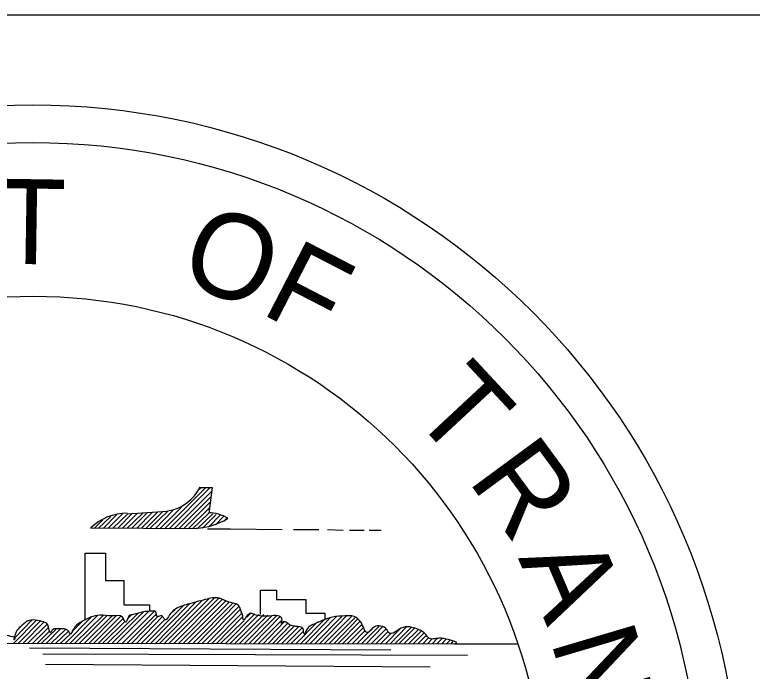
# Model space of a CAD drawing. Extents: x 1458004.1 to 1458040.9, y 194172.7 to 194198.1.
# Drawn here: x 1458033.012 to 1458033.917, y 194177.242 to 194178.047 of the extents above; entities that cross this region are included whole.
import ezdxf

# ---------------------------------------------------------------- set-up
doc = ezdxf.new("R2010")
doc.units = 0
for name, color, linetype in [('ODOT_Seal_0', 7, 'Continuous'), ('ODOT_Seal_1', 7, 'Continuous'), ('ODOT_Seal_2', 7, 'Continuous'), ('Text_Box_4', 7, 'Continuous')]:
    doc.layers.add(name, color=color, linetype=linetype)

msp = doc.modelspace()

# ---------------------------------------------------------------- linework, layer by layer
at = {"layer": 'ODOT_Seal_0'}
for p, q in [((1458033.235, 194177.41667), (1458033.105, 194177.4175)), ((1458033.24833, 194177.41667), (1458033.27667, 194177.41667)), ((1458033.27667, 194177.41667), (1458033.34, 194177.41583)), ((1458033.35417, 194177.41583), (1458033.385, 194177.41583)), ((1458033.39583, 194177.41583), (1458033.415, 194177.415)), ((1458033.4225, 194177.415), (1458033.44083, 194177.415)), ((1458033.44667, 194177.415), (1458033.46167, 194177.415)), ((1458033.09833, 194177.30583), (1458033.09833, 194177.38667)), ((1458033.09833, 194177.38667), (1458033.12333, 194177.38667)), ((1458033.12333, 194177.38667), (1458033.12333, 194177.35333)), ((1458033.12333, 194177.35333), (1458033.14583, 194177.35333)), ((1458033.14583, 194177.35333), (1458033.14583, 194177.32333)), ((1458033.31333, 194177.31167), (1458033.31333, 194177.34167)), ((1458033.31333, 194177.34167), (1458033.33333, 194177.34167)), ((1458033.33333, 194177.34167), (1458033.33333, 194177.33)), ((1458033.17833, 194177.27583), (1458033.22667, 194177.325)), ((1458033.18417, 194177.27583), (1458033.23417, 194177.32667)), ((1458033.18917, 194177.27583), (1458033.2425, 194177.32917)), ((1458033.195, 194177.27583), (1458033.25, 194177.33083)), ((1458033.20083, 194177.27583), (1458033.25667, 194177.33167)), ((1458033.20667, 194177.27583), (1458033.2625, 194177.33167)), ((1458033.2125, 194177.27583), (1458033.26667, 194177.33)), ((1458033.21833, 194177.27583), (1458033.27083, 194177.32833)), ((1458033.22417, 194177.27583), (1458033.275, 194177.32667)), ((1458033.23, 194177.27583), (1458033.27917, 194177.325)), ((1458033.33333, 194177.33), (1458033.36917, 194177.33)), ((1458033.36917, 194177.33), (1458033.36917, 194177.31333)), ((1458033.1375, 194177.27667), (1458033.17667, 194177.31583)), ((1458033.14333, 194177.27583), (1458033.18333, 194177.31583)), ((1458033.14583, 194177.32333), (1458033.1775, 194177.32333)), ((1458033.1725, 194177.27583), (1458033.21833, 194177.32167)), ((1458033.1775, 194177.32333), (1458033.1775, 194177.31667)), ((1458033.20417, 194177.31417), (1458033.20833, 194177.3175)), ((1458033.23583, 194177.27583), (1458033.28333, 194177.32417)), ((1458033.24167, 194177.27583), (1458033.2875, 194177.32167)), ((1458033.2475, 194177.27583), (1458033.28917, 194177.31833)), ((1458033.07417, 194177.27667), (1458033.10667, 194177.30917)), ((1458033.08, 194177.27667), (1458033.11417, 194177.31083)), ((1458033.08583, 194177.27667), (1458033.12083, 194177.31083)), ((1458033.09167, 194177.27667), (1458033.12583, 194177.31083)), ((1458033.0975, 194177.27667), (1458033.13167, 194177.31)), ((1458033.10333, 194177.27667), (1458033.13667, 194177.31)), ((1458033.10917, 194177.27667), (1458033.14167, 194177.30917)), ((1458033.115, 194177.27667), (1458033.145, 194177.30667)), ((1458033.12583, 194177.27667), (1458033.16333, 194177.31333)), ((1458033.13167, 194177.27667), (1458033.17, 194177.315)), ((1458033.14917, 194177.27583), (1458033.18583, 194177.3125)), ((1458033.15083, 194177.30667), (1458033.155, 194177.31083)), ((1458033.155, 194177.27583), (1458033.1875, 194177.30917)), ((1458033.16083, 194177.27583), (1458033.19333, 194177.30917)), ((1458033.25333, 194177.27583), (1458033.29083, 194177.31333)), ((1458033.25917, 194177.27583), (1458033.29167, 194177.30917)), ((1458033.27, 194177.27583), (1458033.30667, 194177.3125)), ((1458033.27583, 194177.27583), (1458033.31167, 194177.31167)), ((1458033.28167, 194177.27583), (1458033.3175, 194177.31167)), ((1458033.2875, 194177.27583), (1458033.3225, 194177.31083)), ((1458033.29333, 194177.27583), (1458033.3275, 194177.31)), ((1458033.29667, 194177.30833), (1458033.30167, 194177.31333)), ((1458033.29917, 194177.27583), (1458033.33333, 194177.31)), ((1458033.305, 194177.27583), (1458033.3375, 194177.30917)), ((1458033.36833, 194177.27583), (1458033.4, 194177.30833)), ((1458033.36917, 194177.31333), (1458033.3925, 194177.31333)), ((1458033.37417, 194177.27583), (1458033.40667, 194177.30917)), ((1458033.38, 194177.27583), (1458033.41333, 194177.30917)), ((1458033.38583, 194177.27583), (1458033.41917, 194177.31)), ((1458033.39167, 194177.27583), (1458033.425, 194177.30917)), ((1458033.3925, 194177.31333), (1458033.3925, 194177.30583)), ((1458033.3975, 194177.27583), (1458033.43, 194177.30833)), ((1458033.40333, 194177.27583), (1458033.43333, 194177.30667)), ((1458033.01083, 194177.27667), (1458033.03917, 194177.305)), ((1458033.0125, 194177.28333), (1458033.03333, 194177.305)), ((1458033.01667, 194177.27667), (1458033.04417, 194177.30417)), ((1458033.01667, 194177.29417), (1458033.02167, 194177.29917)), ((1458033.01667, 194177.29417), (1458033.02167, 194177.29917)), ((1458033.0225, 194177.27667), (1458033.04833, 194177.3025)), ((1458033.02833, 194177.27667), (1458033.05167, 194177.3)), ((1458033.0825, 194177.29083), (1458033.09583, 194177.30417)), ((1458033.12, 194177.27667), (1458033.1475, 194177.30333)), ((1458033.16667, 194177.27583), (1458033.19583, 194177.305)), ((1458033.26417, 194177.27583), (1458033.29333, 194177.30417)), ((1458033.31083, 194177.27583), (1458033.34, 194177.305)), ((1458033.31667, 194177.27583), (1458033.3425, 194177.3025)), ((1458033.3225, 194177.27583), (1458033.34667, 194177.30083)), ((1458033.32833, 194177.27583), (1458033.35083, 194177.29917)), ((1458033.33333, 194177.27583), (1458033.35583, 194177.29833)), ((1458033.35667, 194177.27583), (1458033.38333, 194177.3025)), ((1458033.3625, 194177.27583), (1458033.3925, 194177.30583)), ((1458033.40833, 194177.27583), (1458033.43583, 194177.30333)), ((1458033.41417, 194177.27583), (1458033.4375, 194177.29917)), ((1458033.4375, 194177.27583), (1458033.45917, 194177.2975)), ((1458033.03417, 194177.27667), (1458033.05333, 194177.29583)), ((1458033.04, 194177.27667), (1458033.055, 194177.29167)), ((1458033.045, 194177.27667), (1458033.0625, 194177.29333)), ((1458033.05083, 194177.27667), (1458033.06833, 194177.29417)), ((1458033.05667, 194177.27667), (1458033.07417, 194177.29333)), ((1458033.0625, 194177.27667), (1458033.0775, 194177.29083)), ((1458033.33917, 194177.27583), (1458033.36, 194177.29667)), ((1458033.345, 194177.27583), (1458033.36417, 194177.295)), ((1458033.35083, 194177.27583), (1458033.36667, 194177.29167)), ((1458033.42, 194177.27583), (1458033.44, 194177.29583)), ((1458033.42583, 194177.27583), (1458033.44167, 194177.29167)), ((1458033.43167, 194177.27583), (1458033.45167, 194177.29583)), ((1458033.44333, 194177.27583), (1458033.46333, 194177.29667)), ((1458033.44917, 194177.27583), (1458033.4675, 194177.29417)), ((1458033.455, 194177.27583), (1458033.47, 194177.29083)), ((1458033.46083, 194177.27583), (1458033.47333, 194177.28833)), ((1458033.46667, 194177.27583), (1458033.48583, 194177.295)), ((1458033.4725, 194177.27583), (1458033.4925, 194177.29667)), ((1458033.47833, 194177.27583), (1458033.49833, 194177.29583)), ((1458033.48333, 194177.27583), (1458033.5025, 194177.295)), ((1458033.48917, 194177.27583), (1458033.5075, 194177.29333)), ((1458033.495, 194177.27583), (1458033.51083, 194177.29167)), ((1458033.50083, 194177.27583), (1458033.51417, 194177.28917)), ((1458033.06833, 194177.27667), (1458033.08, 194177.2875)), ((1458033.50667, 194177.27583), (1458033.51667, 194177.28583)), ((1458033.5125, 194177.27583), (1458033.52, 194177.28333)), ((1458033.51833, 194177.27583), (1458033.52417, 194177.28167)), ((1458033.52417, 194177.27583), (1458033.53083, 194177.2825)), ((1458033.53, 194177.27583), (1458033.53667, 194177.2825)), ((1458033.53583, 194177.27583), (1458033.54167, 194177.28167)), ((1458033.54167, 194177.27583), (1458033.54583, 194177.28)), ((1458033.5475, 194177.27583), (1458033.55, 194177.27917)), ((1458032.955, 194177.27667), (1458033.55167, 194177.27583)), ((1458033.03, 194177.27083), (1458033.47333, 194177.26833)), ((1458033.55167, 194177.27583), (1458033.55417, 194177.2775)), ((1458033.55167, 194177.27583), (1458033.62833, 194177.27583)), ((1458033.04667, 194177.26333), (1458033.5675, 194177.26167)), ((1458033.05, 194177.25083), (1458033.52167, 194177.2475))]:
    msp.add_line(p, q, dxfattribs=at)
for points in [[(1458033.23917, 194177.4675), (1458033.25417, 194177.4675), (1458033.25, 194177.43583)], [(1458033.15, 194177.435), (1458033.19917, 194177.43833)]]:
    msp.add_lwpolyline(points, dxfattribs=at)
for centre, radius, start, end in [((1458033.19253, 194177.49013), 0.05185, 277.60916, 335.06674), ((1458033.14968, 194177.37157), 0.06414, 89.81684, 133.60433), ((1458033.24824, 194177.386), 0.05048, 59.78078, 88.39284), ((1458033.2318, 194177.49546), 0.07801, 272.16421, 302.43535), ((1458032.61021, 194173.80526), 3.43948, 78.66952, 89.49057)]:
    msp.add_arc(centre, radius, start, end, dxfattribs=at)
for points in [[(1458033.55417, 194177.2775), (1458033.54417, 194177.28083), (1458033.5325, 194177.2825), (1458033.52583, 194177.28167), (1458033.5225, 194177.28167), (1458033.51417, 194177.28917), (1458033.5075, 194177.29333), (1458033.49917, 194177.29583), (1458033.48833, 194177.29583), (1458033.47083, 194177.28917), (1458033.46833, 194177.29333), (1458033.46083, 194177.2975), (1458033.45333, 194177.29667), (1458033.44333, 194177.29), (1458033.4425, 194177.29083), (1458033.43833, 194177.29917), (1458033.435, 194177.30417), (1458033.42833, 194177.30917), (1458033.4175, 194177.31), (1458033.40167, 194177.30833), (1458033.37917, 194177.3), (1458033.36917, 194177.29083), (1458033.3675, 194177.2875), (1458033.36667, 194177.28917), (1458033.36583, 194177.29417), (1458033.34917, 194177.29917), (1458033.34167, 194177.3025), (1458033.33917, 194177.30083), (1458033.34, 194177.305), (1458033.3375, 194177.30917), (1458033.3275, 194177.31), (1458033.30417, 194177.3125), (1458033.30167, 194177.31333), (1458033.2925, 194177.305), (1458033.29167, 194177.31), (1458033.29, 194177.315), (1458033.28667, 194177.3225), (1458033.275, 194177.32667), (1458033.26333, 194177.33167), (1458033.24583, 194177.33), (1458033.22417, 194177.32417), (1458033.20917, 194177.31833), (1458033.205, 194177.315), (1458033.19917, 194177.30667), (1458033.1975, 194177.305), (1458033.19333, 194177.30917), (1458033.19083, 194177.31), (1458033.18667, 194177.30917), (1458033.185, 194177.315), (1458033.18333, 194177.31583), (1458033.18083, 194177.31583), (1458033.17, 194177.315), (1458033.1575, 194177.31167), (1458033.1525, 194177.31), (1458033.15, 194177.305), (1458033.1475, 194177.30167)], [(1458033.1475, 194177.30167), (1458033.14667, 194177.30333), (1458033.14417, 194177.30833), (1458033.13083, 194177.31), (1458033.11667, 194177.31083), (1458033.105, 194177.30833), (1458033.095, 194177.30333), (1458033.08583, 194177.29667), (1458033.08167, 194177.28917), (1458033.08, 194177.2875), (1458033.07917, 194177.28917), (1458033.075, 194177.29333), (1458033.07083, 194177.29417), (1458033.06417, 194177.29417), (1458033.05917, 194177.29333), (1458033.05583, 194177.28917), (1458033.0525, 194177.29917), (1458033.0475, 194177.3025), (1458033.0275, 194177.30333), (1458033.01917, 194177.29667), (1458033.01333, 194177.28917), (1458033.01167, 194177.28083), (1458033.0125, 194177.2825), (1458033.01, 194177.28417), (1458033, 194177.28667), (1458032.995, 194177.2875), (1458032.99083, 194177.28333), (1458032.99083, 194177.2875), (1458032.97417, 194177.29), (1458032.96917, 194177.29), (1458032.96, 194177.28667), (1458032.955, 194177.27667)]]:
    msp.add_spline(points, degree=3, dxfattribs=at)
at = {"layer": 'ODOT_Seal_1'}
for p, q in [((1458033.19583, 194177.41667), (1458033.24667, 194177.4675)), ((1458033.20167, 194177.41667), (1458033.25167, 194177.4675)), ((1458033.2075, 194177.41667), (1458033.25333, 194177.4625)), ((1458033.23833, 194177.465), (1458033.24083, 194177.4675)), ((1458033.21333, 194177.41667), (1458033.2525, 194177.45583)), ((1458033.19, 194177.41667), (1458033.21667, 194177.44333)), ((1458033.21917, 194177.41667), (1458033.25167, 194177.44917)), ((1458033.225, 194177.41667), (1458033.25083, 194177.4425)), ((1458033.12083, 194177.4175), (1458033.1375, 194177.43417)), ((1458033.12667, 194177.4175), (1458033.14417, 194177.435)), ((1458033.1325, 194177.4175), (1458033.15083, 194177.435)), ((1458033.13833, 194177.4175), (1458033.15667, 194177.43583)), ((1458033.14417, 194177.4175), (1458033.1625, 194177.43583)), ((1458033.15, 194177.4175), (1458033.16917, 194177.43583)), ((1458033.15583, 194177.4175), (1458033.175, 194177.43667)), ((1458033.16167, 194177.4175), (1458033.18083, 194177.43667)), ((1458033.1675, 194177.4175), (1458033.1875, 194177.4375)), ((1458033.17333, 194177.4175), (1458033.19333, 194177.4375)), ((1458033.17833, 194177.4175), (1458033.2, 194177.43833)), ((1458033.18417, 194177.41667), (1458033.20667, 194177.44)), ((1458033.23, 194177.41667), (1458033.25, 194177.43583)), ((1458033.23583, 194177.41667), (1458033.255, 194177.435)), ((1458033.2425, 194177.4175), (1458033.25917, 194177.43417)), ((1458033.25, 194177.41917), (1458033.26417, 194177.43333)), ((1458033.11, 194177.4175), (1458033.12, 194177.4275)), ((1458033.115, 194177.4175), (1458033.13, 194177.43167)), ((1458033.25833, 194177.42167), (1458033.26833, 194177.43167)), ((1458033.26833, 194177.42583), (1458033.2725, 194177.43))]:
    msp.add_line(p, q, dxfattribs=at)
for centre, radius in [((1458033.03411, 194177.07063), 0.81946), ((1458033.03503, 194177.07441), 0.6273)]:
    msp.add_circle(centre, radius, dxfattribs=at)
at = {"layer": 'ODOT_Seal_2'}
msp.add_circle((1458033.03418, 194177.069), 0.86723, dxfattribs=at)
at = {"layer": 'Text_Box_4'}
msp.add_line((1458032.09667, 194178.04667), (1458039.4, 194178.04667), dxfattribs=at)

# ---------------------------------------------------------------- texts
at = {"layer": 'ODOT_Seal_1'}
for s, height, rotation, p in [('T', 0.10413, 359.14617, (1458032.98917, 194177.74167)), ('O', 0.10412, 339.33591, (1458033.21, 194177.72083)), ('F', 0.10411, 332.73249, (1458033.31167, 194177.68167)), ('T', 0.10412, 312.92223, (1458033.49583, 194177.55833)), ('R', 0.10412, 306.31881, (1458033.56667, 194177.47667)), ('A', 0.10412, 293.11197, (1458033.62917, 194177.38083)), ('N', 0.10413, 286.50855, (1458033.66917, 194177.28))]:
    msp.add_text(s, height=height, rotation=rotation, dxfattribs=at).set_placement(p)

doc.saveas('drawing.dxf')
